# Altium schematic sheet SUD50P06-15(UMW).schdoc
size 127 x 101 mm
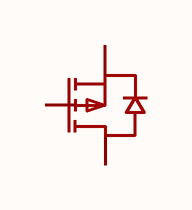
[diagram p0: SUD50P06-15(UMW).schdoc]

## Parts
Q?  sud50p06-15(umw)  [TO-252-2_L6.6-W6.1-P4.58-LS9.9-TL]  (value not drawn)

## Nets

Not connected (* = marked no-connect by the designer): Q? 1(G) 2(D) 3(S)

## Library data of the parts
Q? = sud50p06-15(umw): 漏源电压(Vdss):60V;连续漏极电流(Id):50A;导通电阻(RDS(on)):12mΩ@10V;耗散功率(Pd):2.5W;阈值电压(Vgs(th)):1.8V@250uA;; Manufacturer: UMW(友台半导体); AddInBom: yes; ModelId: ce57f84d66384067af8a68020b6de06d; ModelName: TO-252-2L-3P_L6.6-W6.1-H2.3-LS10.1-P4.6; ModelTransform: 259.842,390.52442,0,270,0,0,39.372,0.002,0; Drain to Source Voltage: 60V; Current - Continuous Drain(Id): 50A; Pd - Power Dissipation: 2.5W; Gate Charge(Qg): 110nC@10V; Input Capacitance(Ciss): 4.95nF@25V; Reverse Transfer Capacitance (Crss@Vds): 405pF@25V; Type: P沟道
